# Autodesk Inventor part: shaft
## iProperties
Author: GJOHNST2
Shininess: 20.0
Length Units: 11272
Angle Units: 11286
Time Units: 11279
Mass Units: 11290
Length Display Precision: 3
Angle Display Precision: 2
Compacted: True
PropertySet Name: _Private Model Information
Created: 2001-11
Part Number: shaft
Material: Bronze, Soft Tin
Document SubType Name: Modeling
Designer: GJOHNST2
Control State: 0
Master: False
Checked Out: False
PropertySet Name: Design Tracking Control
Density: 8.874
Volumn: 69.31152758254692
Area: 154.936368119388
PropertySet Name: Model Information
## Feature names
1. Extrusion1
2. Hole1
3. Chamfer1
4. Extrusion2
